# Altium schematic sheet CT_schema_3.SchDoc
size 445 x 328 mm
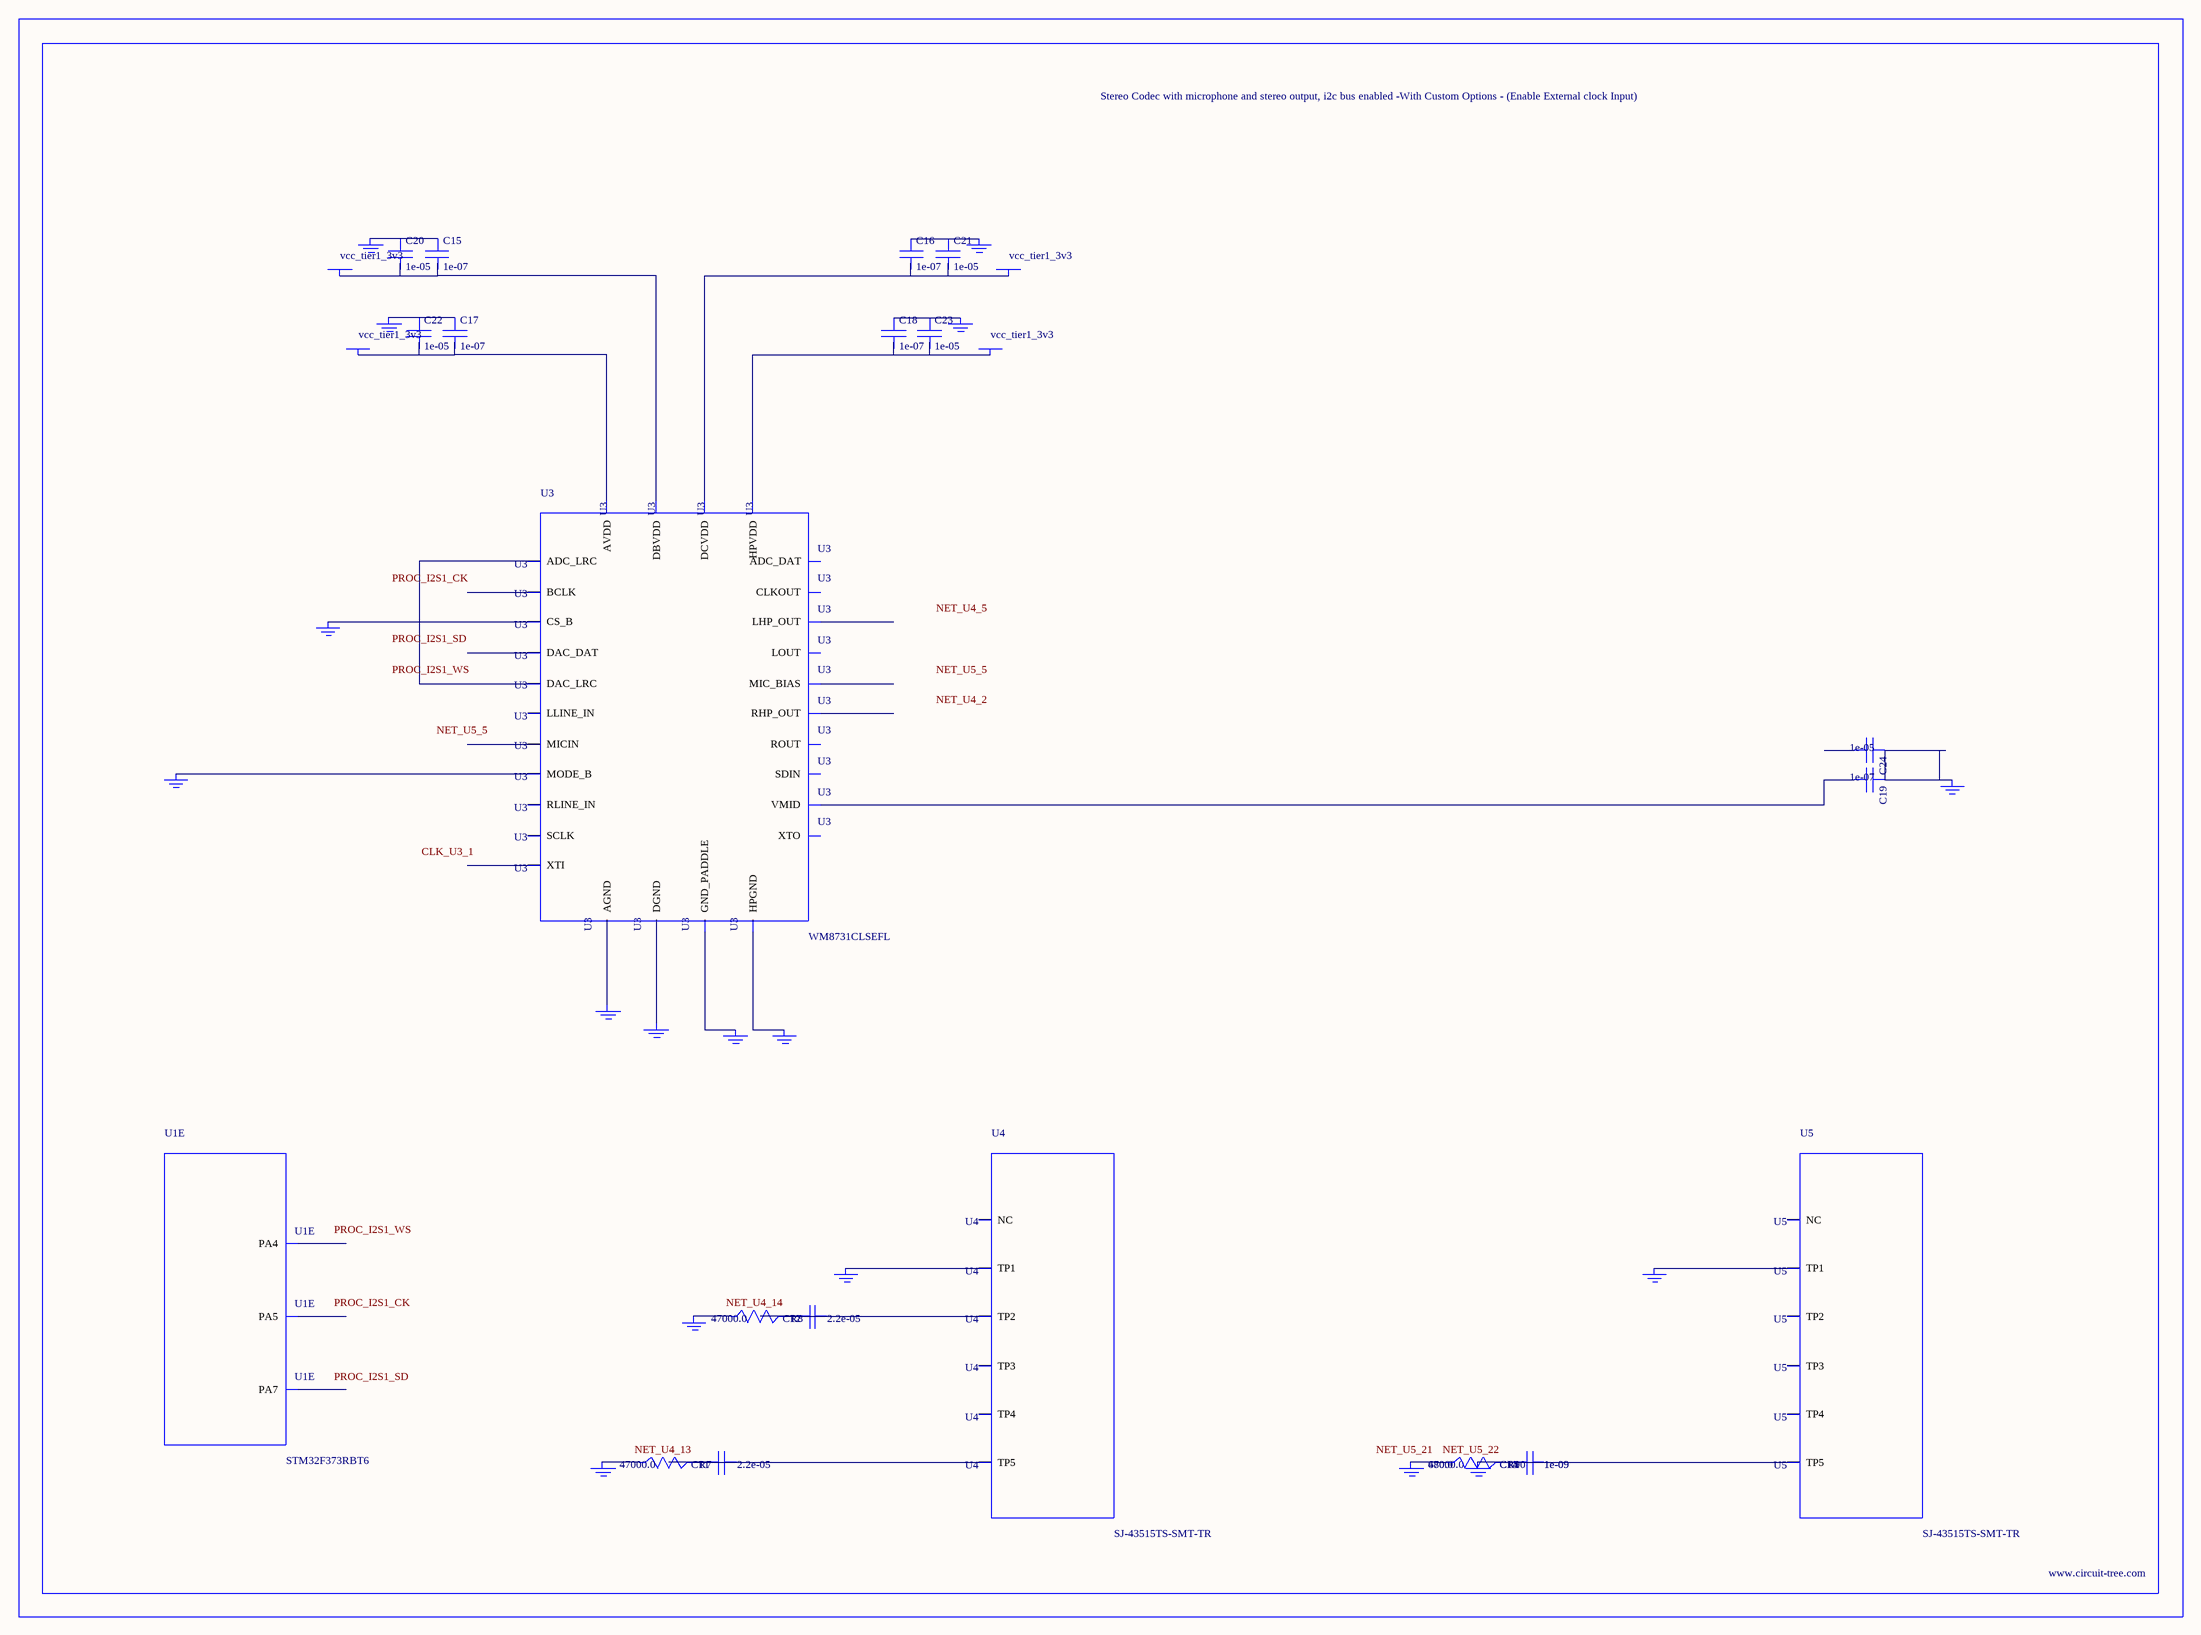
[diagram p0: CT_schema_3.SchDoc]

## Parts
BORDER2  (no value)
C11  2.2e-05  [C1210]
C12  2.2e-05  [C1210]
C13  1e-09  [C0402]
C14  1e-09  [C0402]
C15  1e-07  [C0402]
C16  1e-07  [C0402]
C17  1e-07  [C0402]
C18  1e-07  [C0402]
C19  1e-07  [C0402]
C20  1e-05  [C0805]
C21  1e-05  [C0805]
C22  1e-05  [C0805]
C23  1e-05  [C0805]
C24  1e-05  [C0805]
GND_INSTANCE_2_0  (no value)
GND_INSTANCE_2_1  (no value)
GND_INSTANCE_2_2  (no value)
GND_INSTANCE_2_3  (no value)
GND_INSTANCE_2_4  (no value)
GND_INSTANCE_2_5  (no value)
GND_INSTANCE_2_6  (no value)
GND_INSTANCE_2_7  (no value)
GND_INSTANCE_2_8  (no value)
GND_INSTANCE_2_9  (no value)
GND_INSTANCE_2_10  (no value)
GND_INSTANCE_2_11  (no value)
GND_INSTANCE_2_12  (no value)
GND_INSTANCE_2_13  (no value)
GND_INSTANCE_2_14  (no value)
GND_INSTANCE_2_15  (no value)
GND_INSTANCE_2_16  (no value)
POWER_INSTANCE_2_0  vcc_tier1_3v3
POWER_INSTANCE_2_1  vcc_tier1_3v3
POWER_INSTANCE_2_2  vcc_tier1_3v3
POWER_INSTANCE_2_3  vcc_tier1_3v3
R7  47000.0  [R0603]
R8  47000.0  [R0603]
R9  47000.0  [R0603]
R10  680.0  [R0603]
U1  STM32F373RBT6  [LQFP64]  (part E of 6)
U3  WM8731CLSEFL  [QFN-28]
U4  SJ-43515TS-SMT-TR  [SJ-43515TS-SMT-TR]
U5  SJ-43515TS-SMT-TR  [SJ-43515TS-SMT-TR]

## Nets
NetC11_1: C11.1 C11.2 R7.2 U4.5(TP5)
NetC12_1: C12.1 C12.2 R8.2 U4.2(TP2)
NetC13_1: C13.1 C13.2 C14.1 C14.2 GND_INSTANCE_2_16.0(GND) R9.2 R10.2 U5.5(TP5)
NetC15_1: C15.1 C20.1 GND_INSTANCE_2_1.0(GND)
NetC15_2: C15.2 C20.2 POWER_INSTANCE_2_1.0(PWR) U3.5(DBVDD)
NetC16_1: C16.1 C21.1 GND_INSTANCE_2_0.0(GND)
NetC16_2: C16.2 C21.2 POWER_INSTANCE_2_0.0(PWR) U3.3(DCVDD)
NetC17_1: C17.1 C22.1 GND_INSTANCE_2_4.0(GND)
NetC17_2: C17.2 C22.2 POWER_INSTANCE_2_3.0(PWR) U3.18(AVDD)
NetC18_1: C18.1 C23.1 GND_INSTANCE_2_2.0(GND)
NetC18_2: C18.2 C23.2 POWER_INSTANCE_2_2.0(PWR) U3.12(HPVDD)
NetC19_1: C19.1 C24.1 GND_INSTANCE_2_5.0(GND)
NetC19_2: C19.2 U3.20(VMID)
NetGND_INSTANCE_2_3_0: GND_INSTANCE_2_3.0(GND) U3.15(HPGND)
NetGND_INSTANCE_2_6_0: GND_INSTANCE_2_6.0(GND) U3.25(MODE_B)
NetGND_INSTANCE_2_7_0: GND_INSTANCE_2_7.0(GND) U3.26(CS_B)
NetGND_INSTANCE_2_8_0: GND_INSTANCE_2_8.0(GND) U3.29(GND_PADDLE)
NetGND_INSTANCE_2_9_0: GND_INSTANCE_2_9.0(GND) U3.4(DGND)
NetGND_INSTANCE_2_10_0: GND_INSTANCE_2_10.0(GND) U3.19(AGND)
NetGND_INSTANCE_2_11_0: GND_INSTANCE_2_11.0(GND) U4.1(TP1)
NetGND_INSTANCE_2_12_0: GND_INSTANCE_2_12.0(GND) R8.1
NetGND_INSTANCE_2_13_0: GND_INSTANCE_2_13.0(GND) R7.1
NetGND_INSTANCE_2_14_0: GND_INSTANCE_2_14.0(GND) U5.1(TP1)
NetGND_INSTANCE_2_15_0: GND_INSTANCE_2_15.0(GND) R9.1 R10.1
NetU3_9: U3.9(DAC_LRC) U3.11(ADC_LRC)

Not connected (* = marked no-connect by the designer): C24 2; U1 20(PA4) 21(PA5) 23(PA7); U3 1(XTI) 2(XTO) 6(CLKOUT) 7(BCLK) 8(DAC_DAT) 10(ADC_DAT) 13(LHP_OUT) 14(RHP_OUT) 16(LOUT) 17(ROUT) 21(MIC_BIAS) 22(MICIN) 23(RLINE_IN) 24(LLINE_IN) 27(SDIN) 28(SCLK); U4 3(TP3) 4(TP4) 6(NC); U5 2(TP2) 3(TP3) 4(TP4) 6(NC)

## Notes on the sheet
- Labels drawn without touching a wire or pin: CLK_U3_1, NET_U4_2, NET_U4_5, NET_U4_13, NET_U4_14, NET_U5_5, NET_U5_21, NET_U5_22, PROC_I2S1_CK, PROC_I2S1_SD, PROC_I2S1_WS

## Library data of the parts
BORDER2 = BORDER_PAGE2
C11 C12 = C1210C224K5RACTU
C13 C14 = C0402C102K3RAC
C15-C19 = C0402C104K3RACTU
C20-C24 = C0805C106K8RACTU
GND_INSTANCE_2_0-GND_INSTANCE_2_16 = GND
POWER_INSTANCE_2_0-POWER_INSTANCE_2_3 = PWR
R7-R9 = RC0603JR-0747KL
R10 = RC0603JR-07680RL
